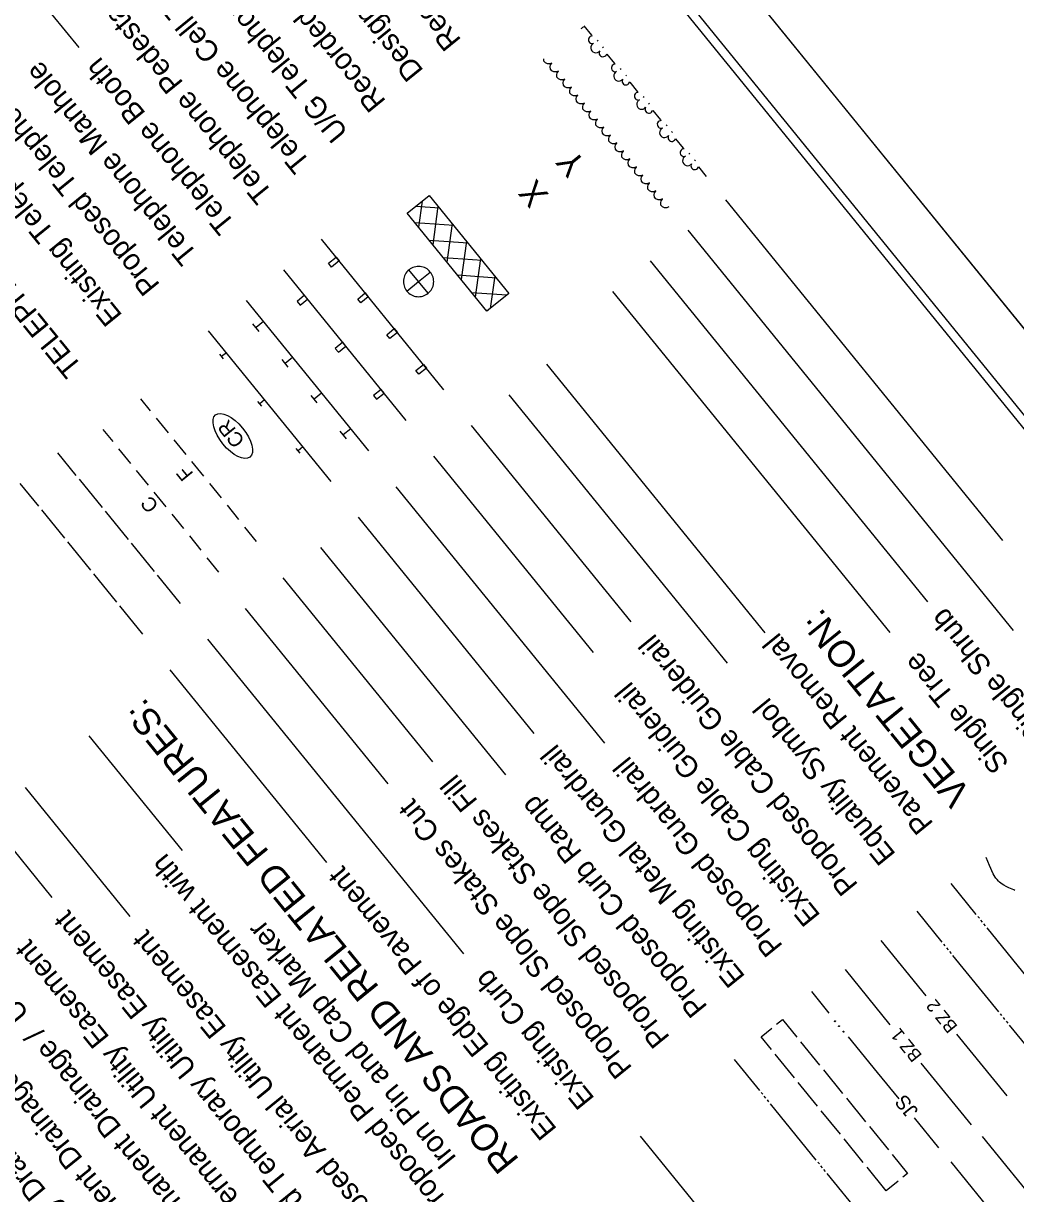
# Model space of a CAD drawing. Extents: x 2596486 to 2602076, y 851390 to 856110.
# Drawn here: x 2599844.2 to 2600253.1, y 854986.6 to 855469.1 of the extents above; entities that cross this region are included whole.
import ezdxf

# ---------------------------------------------------------------- set-up
doc = ezdxf.new("R2010")
doc.units = 0
for name, color, linetype in [('Prop WCC CELL', 7, 'Continuous'), ('Sheet Cutting Line CELL', 7, 'Continuous'), ('Sheet Plot Border Inside CELL', 7, 'Continuous'), ('Sheet Plot Border Outside CELL', 7, 'Continuous'), ('Sheet Symbology CELL', 7, 'Continuous')]:
    doc.layers.add(name, color=color, linetype=linetype)

msp = doc.modelspace()

# ---------------------------------------------------------------- linework, layer by layer
at = {"layer": 'Prop WCC CELL'}
msp.add_ellipse((2599930.44, 855298.98), major_axis=(-7.07, 8.7), ratio=0.462467, dxfattribs=at)
at = {"layer": 'Sheet Cutting Line CELL'}
msp.add_line((2600696, 854802.71), (2599633.88, 856109.52), dxfattribs=at)
at = {"layer": 'Sheet Plot Border Inside CELL'}
msp.add_lwpolyline([(2600670.38, 854798.64), (2599619.29, 856091.87), (2598800.52, 855426.4), (2599851.6, 854133.17)], close=True, dxfattribs=at)
at = {"layer": 'Sheet Plot Border Outside CELL'}
msp.add_lwpolyline([(2600696, 854802.71), (2599633.88, 856109.52), (2598780.26, 855415.74), (2599842.38, 854108.93)], close=True, dxfattribs=at)
at = {"layer": 'Sheet Symbology CELL'}
for p, q in [((2599772.04, 855575.95), (2599866.96, 855459.16)), ((2600078.45, 855464.23), (2600075.3, 855468.11)), ((2600081.08, 855461.79), (2600080.77, 855462.18)), ((2600083.29, 855459.07), (2600082.97, 855459.46)), ((2600058.61, 855454.48), (2600058.62, 855454.55)), ((2600087.91, 855452.59), (2600084.76, 855456.47)), ((2600058.73, 855453.54), (2600058.61, 855454.48)), ((2600059.32, 855452.8), (2600058.73, 855453.54)), ((2600060.18, 855452.47), (2600059.32, 855452.8)), ((2600061.06, 855452.41), (2600060.18, 855452.47)), ((2600061.99, 855452.78), (2600061.06, 855452.41)), ((2600061.29, 855451.18), (2600061.45, 855452.02)), ((2600061.41, 855450.24), (2600061.29, 855451.18)), ((2600062, 855449.51), (2600061.41, 855450.24)), ((2600061.45, 855452.02), (2600061.98, 855452.71)), ((2600090.54, 855450.15), (2600090.23, 855450.54)), ((2600062.86, 855449.17), (2600062, 855449.51)), ((2600063.74, 855449.11), (2600062.86, 855449.17)), ((2600064.67, 855449.48), (2600063.74, 855449.11)), ((2600063.97, 855447.88), (2600064.13, 855448.72)), ((2600064.09, 855446.94), (2600063.97, 855447.88)), ((2600064.69, 855446.21), (2600064.09, 855446.94)), ((2600064.13, 855448.72), (2600064.66, 855449.41)), ((2600065.54, 855445.87), (2600064.69, 855446.21)), ((2600066.42, 855445.81), (2600065.54, 855445.87)), ((2600067.35, 855446.18), (2600066.42, 855445.81)), ((2600066.65, 855444.58), (2600066.81, 855445.42)), ((2600066.81, 855445.42), (2600067.34, 855446.11)), ((2600092.75, 855447.43), (2600092.43, 855447.82)), ((2600066.77, 855443.65), (2600066.65, 855444.58)), ((2600067.37, 855442.91), (2600066.77, 855443.65)), ((2600068.22, 855442.57), (2600067.37, 855442.91)), ((2600069.1, 855442.52), (2600068.22, 855442.57)), ((2600070.03, 855442.88), (2600069.1, 855442.52)), ((2600069.33, 855441.28), (2600069.49, 855442.12)), ((2600069.45, 855440.35), (2600069.33, 855441.28)), ((2600070.05, 855439.61), (2600069.45, 855440.35)), ((2600069.49, 855442.12), (2600070.02, 855442.81)), ((2600097.38, 855440.95), (2600094.22, 855444.83)), ((2600070.9, 855439.27), (2600070.05, 855439.61)), ((2600071.78, 855439.22), (2600070.9, 855439.27)), ((2600072.71, 855439.58), (2600071.78, 855439.22)), ((2600072.01, 855437.99), (2600072.17, 855438.82)), ((2600072.13, 855437.05), (2600072.01, 855437.99)), ((2600072.73, 855436.31), (2600072.13, 855437.05)), ((2600072.17, 855438.82), (2600072.7, 855439.51)), ((2600073.58, 855435.98), (2600072.73, 855436.31)), ((2600074.46, 855435.92), (2600073.58, 855435.98)), ((2600075.39, 855436.29), (2600074.46, 855435.92)), ((2600074.69, 855434.69), (2600074.85, 855435.52)), ((2600074.85, 855435.52), (2600075.38, 855436.22)), ((2600100, 855438.51), (2600099.69, 855438.9)), ((2600102.21, 855435.79), (2600101.89, 855436.18)), ((2600074.81, 855433.75), (2600074.69, 855434.69)), ((2600075.41, 855433.01), (2600074.81, 855433.75)), ((2600076.26, 855432.68), (2600075.41, 855433.01)), ((2600077.14, 855432.62), (2600076.26, 855432.68)), ((2600078.07, 855432.99), (2600077.14, 855432.62)), ((2600077.37, 855431.39), (2600077.53, 855432.23)), ((2600077.49, 855430.45), (2600077.37, 855431.39)), ((2600078.09, 855429.72), (2600077.49, 855430.45)), ((2600077.53, 855432.23), (2600078.06, 855432.92)), ((2600106.84, 855429.31), (2600103.68, 855433.19)), ((2600078.94, 855429.38), (2600078.09, 855429.72)), ((2600079.82, 855429.32), (2600078.94, 855429.38)), ((2600080.75, 855429.69), (2600079.82, 855429.32)), ((2600080.05, 855428.09), (2600080.21, 855428.93)), ((2600080.17, 855427.16), (2600080.05, 855428.09)), ((2600080.77, 855426.42), (2600080.17, 855427.16)), ((2600080.21, 855428.93), (2600080.74, 855429.62)), ((2600081.62, 855426.08), (2600080.77, 855426.42)), ((2600082.51, 855426.03), (2600081.62, 855426.08)), ((2600083.43, 855426.39), (2600082.51, 855426.03)), ((2600082.73, 855424.79), (2600082.89, 855425.63)), ((2600082.89, 855425.63), (2600083.42, 855426.32)), ((2600109.46, 855426.87), (2600109.15, 855427.25)), ((2600082.85, 855423.86), (2600082.73, 855424.79)), ((2600083.45, 855423.12), (2600082.85, 855423.86)), ((2600084.3, 855422.78), (2600083.45, 855423.12)), ((2600085.19, 855422.73), (2600084.3, 855422.78)), ((2600086.11, 855423.09), (2600085.19, 855422.73)), ((2600085.41, 855421.5), (2600085.57, 855422.33)), ((2600085.53, 855420.56), (2600085.41, 855421.5)), ((2600085.57, 855422.33), (2600086.1, 855423.02)), ((2600111.67, 855424.15), (2600111.36, 855424.54)), ((2600116.3, 855417.67), (2600113.14, 855421.55)), ((2600086.13, 855419.82), (2600085.53, 855420.56)), ((2600086.98, 855419.49), (2600086.13, 855419.82)), ((2600087.87, 855419.43), (2600086.98, 855419.49)), ((2600088.79, 855419.8), (2600087.87, 855419.43)), ((2600088.09, 855418.2), (2600088.25, 855419.03)), ((2600088.21, 855417.26), (2600088.09, 855418.2)), ((2600088.81, 855416.52), (2600088.21, 855417.26)), ((2600088.25, 855419.03), (2600088.79, 855419.73)), ((2600089.66, 855416.19), (2600088.81, 855416.52)), ((2600090.55, 855416.13), (2600089.66, 855416.19)), ((2600091.47, 855416.5), (2600090.55, 855416.13)), ((2600090.93, 855415.74), (2600091.47, 855416.43)), ((2600090.78, 855414.9), (2600090.93, 855415.74)), ((2600090.89, 855413.96), (2600090.78, 855414.9)), ((2600091.49, 855413.23), (2600090.89, 855413.96)), ((2600092.34, 855412.89), (2600091.49, 855413.23)), ((2600093.23, 855412.83), (2600092.34, 855412.89)), ((2600094.15, 855413.2), (2600093.23, 855412.83)), ((2600093.46, 855411.6), (2600093.61, 855412.44)), ((2600093.57, 855410.67), (2600093.46, 855411.6)), ((2600093.61, 855412.44), (2600094.15, 855413.13)), ((2600118.92, 855415.23), (2600118.61, 855415.61)), ((2600121.13, 855412.51), (2600120.82, 855412.9)), ((2600094.17, 855409.93), (2600093.57, 855410.67)), ((2600095.03, 855409.59), (2600094.17, 855409.93)), ((2600095.91, 855409.54), (2600095.03, 855409.59)), ((2600096.83, 855409.9), (2600095.91, 855409.54)), ((2600096.14, 855408.3), (2600096.29, 855409.14)), ((2600096.25, 855407.37), (2600096.14, 855408.3)), ((2600096.85, 855406.63), (2600096.25, 855407.37)), ((2600096.29, 855409.14), (2600096.83, 855409.83)), ((2600097.71, 855406.29), (2600096.85, 855406.63)), ((2600098.59, 855406.24), (2600097.71, 855406.29)), ((2600099.51, 855406.6), (2600098.59, 855406.24)), ((2600098.97, 855405.84), (2600099.51, 855406.53)), ((2600125.76, 855406.03), (2600122.6, 855409.91)), ((2600098.82, 855405.01), (2600098.97, 855405.84)), ((2600098.93, 855404.07), (2600098.82, 855405.01)), ((2600099.53, 855403.33), (2600098.93, 855404.07)), ((2600100.39, 855403), (2600099.53, 855403.33)), ((2600101.27, 855402.94), (2600100.39, 855403)), ((2600102.2, 855403.31), (2600101.27, 855402.94)), ((2600101.5, 855401.71), (2600101.65, 855402.54)), ((2600101.61, 855400.77), (2600101.5, 855401.71)), ((2600101.65, 855402.54), (2600102.19, 855403.24)), ((2600002.34, 855390.83), (2600011.42, 855398.21)), ((2600011.42, 855398.21), (2600044.28, 855357.78)), ((2600102.21, 855400.03), (2600101.61, 855400.77)), ((2600103.07, 855399.7), (2600102.21, 855400.03)), ((2600103.95, 855399.64), (2600103.07, 855399.7)), ((2600104.88, 855400.01), (2600103.95, 855399.64)), ((2600104.18, 855398.41), (2600104.34, 855399.25)), ((2600104.29, 855397.47), (2600104.18, 855398.41)), ((2600104.89, 855396.74), (2600104.29, 855397.47)), ((2600104.34, 855399.25), (2600104.87, 855399.94)), ((2600105.75, 855396.4), (2600104.89, 855396.74)), ((2600107.56, 855396.71), (2600106.63, 855396.34)), ((2600107.02, 855395.95), (2600107.55, 855396.64)), ((2600015.74, 855392.9), (2600005.75, 855393.61)), ((2600008.51, 855395.85), (2600007.04, 855385.05)), ((2600015.01, 855393.79), (2600012.9, 855377.83)), ((2600106.63, 855396.34), (2600105.75, 855396.4)), ((2600106.86, 855395.11), (2600107.02, 855395.95)), ((2600106.97, 855394.18), (2600106.86, 855395.11)), ((2600107.57, 855393.44), (2600106.97, 855394.18)), ((2600108.43, 855393.1), (2600107.57, 855393.44)), ((2600109.31, 855393.05), (2600108.43, 855393.1)), ((2600110.24, 855393.41), (2600109.31, 855393.05)), ((2600133.57, 855396.41), (2600247.81, 855255.85)), ((2600035.2, 855350.4), (2600002.34, 855390.83)), ((2600021.57, 855385.72), (2600005.59, 855386.84)), ((2600020.88, 855386.57), (2600018.74, 855370.66)), ((2600118.05, 855383.79), (2600252.2, 855218.75)), ((2600017.51, 855318.04), (2599967.05, 855380.13)), ((2600027.44, 855378.5), (2600011.42, 855379.66)), ((2600026.75, 855379.35), (2600024.57, 855363.48)), ((2600033.31, 855371.28), (2600017.26, 855372.48)), ((2600032.58, 855372.18), (2600030.44, 855356.26)), ((2600102.53, 855371.18), (2600216.77, 855230.62)), ((2600001.99, 855305.43), (2599951.53, 855367.51)), ((2600007.04, 855362.66), (2600003.09, 855367.51)), ((2600007.04, 855362.66), (2600011.89, 855366.6)), ((2600039.14, 855364.11), (2600023.12, 855365.26)), ((2600038.45, 855364.96), (2600036.6, 855351.54)), ((2600002.19, 855358.72), (2600007.04, 855362.66)), ((2600010.98, 855357.81), (2600007.04, 855362.66)), ((2600043.39, 855357.06), (2600028.99, 855358.05)), ((2600087.01, 855358.57), (2600201.25, 855218.01)), ((2599936.01, 855354.9), (2599986.47, 855292.82)), ((2600044.28, 855357.78), (2600035.2, 855350.4)), ((2600035.67, 855350.78), (2600034.85, 855350.83)), ((2599941.32, 855342.1), (2599938.79, 855345.21)), ((2599943.12, 855346.15), (2599940.06, 855343.66)), ((2599970.95, 855280.2), (2599920.49, 855342.28)), ((2599926.66, 855330.73), (2599925.09, 855332.67)), ((2599927.81, 855333.27), (2599925.87, 855331.7)), ((2599953.3, 855327.36), (2599950.78, 855330.46)), ((2599955.1, 855331.4), (2599952.04, 855328.91)), ((2600059.79, 855328.53), (2600149.74, 855217.85)), ((2599965.28, 855312.62), (2599962.76, 855315.72)), ((2599967.09, 855316.66), (2599964.02, 855314.17)), ((2600044.27, 855315.92), (2600134.22, 855205.24)), ((2599892.43, 855314.33), (2599896.47, 855309.36)), ((2599942.43, 855311.32), (2599940.85, 855313.26)), ((2599943.58, 855313.87), (2599941.64, 855312.29)), ((2599898.93, 855306.34), (2599903.88, 855300.25)), ((2599876.91, 855301.72), (2599880.95, 855296.75)), ((2599977.27, 855297.87), (2599974.75, 855300.98)), ((2599979.07, 855301.92), (2599976.01, 855299.42)), ((2600028.75, 855303.3), (2600094.53, 855222.36)), ((2599906.21, 855297.38), (2599911.1, 855291.36)), ((2599865.97, 855282.71), (2599858.4, 855292.02)), ((2599883.41, 855293.72), (2599888.36, 855287.63)), ((2599958.2, 855291.92), (2599956.62, 855293.86)), ((2599959.35, 855294.47), (2599957.41, 855292.89)), ((2600013.23, 855290.69), (2600079.01, 855209.75)), ((2599913.43, 855288.49), (2599918.35, 855282.44)), ((2599876.69, 855269.52), (2599867.23, 855281.16)), ((2599890.69, 855284.76), (2599895.58, 855278.75)), ((2599850.45, 855270.1), (2599842.88, 855279.41)), ((2599920.84, 855279.37), (2599925.64, 855273.47)), ((2599997.71, 855278.07), (2600083.63, 855172.35)), ((2599897.91, 855275.88), (2599902.83, 855269.82)), ((2599861.17, 855256.9), (2599851.71, 855268.54)), ((2599887.42, 855256.33), (2599877.95, 855267.97)), ((2599905.32, 855266.76), (2599910.12, 855260.86)), ((2599928.1, 855270.45), (2599932.86, 855264.59)), ((2599982.19, 855265.46), (2600054.62, 855176.34)), ((2599912.58, 855257.83), (2599917.34, 855251.97)), ((2599940.27, 855255.47), (2599935.48, 855261.37)), ((2599871.9, 855243.71), (2599862.43, 855255.35)), ((2599898.14, 855243.13), (2599888.68, 855254.77)), ((2599966.66, 855253.04), (2600042.93, 855159.2)), ((2599924.75, 855242.86), (2599919.96, 855248.75)), ((2599882.62, 855230.52), (2599873.16, 855242.16)), ((2599908.86, 855229.94), (2599899.4, 855241.58)), ((2599951.14, 855240.43), (2600012.79, 855164.58)), ((2599893.34, 855217.33), (2599883.88, 855228.97)), ((2599935.62, 855227.81), (2599994.4, 855155.5)), ((2599920.1, 855215.2), (2600025.52, 855085.49)), ((2599904.58, 855202.59), (2599969.13, 855123.16)), ((2599871.09, 855175.37), (2599909.57, 855128.02)), ((2599844.84, 855154.03), (2599888.02, 855100.91)), ((2599829.32, 855141.42), (2599855.9, 855108.72)), ((2600236.95, 855101.66), (2600226.56, 855114.44)), ((2600222.89, 855090.23), (2600212.5, 855103.01)), ((2600238.22, 855100.1), (2600237.58, 855100.88)), ((2600239.48, 855098.55), (2600238.85, 855099.33)), ((2600240.74, 855097), (2600240.11, 855097.78)), ((2600260.29, 855072.94), (2600241.37, 855096.22)), ((2600197.61, 855090.91), (2600216.09, 855068.16)), ((2600224.16, 855088.68), (2600223.53, 855089.45)), ((2600225.42, 855087.12), (2600224.79, 855087.9)), ((2600226.68, 855085.57), (2600226.05, 855086.35)), ((2600246.23, 855061.52), (2600227.31, 855084.8)), ((2600182.88, 855078.94), (2600201.36, 855056.2)), ((2600247.49, 855059.96), (2600246.86, 855060.74)), ((2600248.75, 855058.41), (2600248.12, 855059.19)), ((2600250.02, 855056.86), (2600249.38, 855057.64)), ((2600264.54, 855038.99), (2600250.65, 855056.08)), ((2600164.48, 855049.21), (2600172.36, 855039.51)), ((2600249.64, 855026.89), (2600228.96, 855052.33)), ((2600147.66, 855029.08), (2600137.27, 855041.86)), ((2600161.98, 855034.33), (2600154.1, 855044.03)), ((2600234.91, 855014.92), (2600214.23, 855040.36)), ((2600173.94, 855037.57), (2600181.82, 855027.87)), ((2600171.44, 855022.69), (2600163.56, 855032.39)), ((2600148.92, 855027.53), (2600148.29, 855028.3)), ((2600150.18, 855025.97), (2600149.55, 855026.75)), ((2600151.44, 855024.42), (2600150.81, 855025.2)), ((2600183.4, 855025.93), (2600191.28, 855016.23)), ((2600170.99, 855000.37), (2600152.07, 855023.65)), ((2600180.9, 855011.05), (2600173.02, 855020.75)), ((2600192.86, 855014.29), (2600200.74, 855004.59)), ((2600148.92, 854948.25), (2600098.47, 855010.33)), ((2600190.36, 854999.41), (2600182.48, 855009.11)), ((2600239.36, 855010.13), (2600342.64, 854883.06)), ((2600172.25, 854998.81), (2600171.62, 854999.59)), ((2600173.52, 854997.26), (2600172.89, 854998.04)), ((2600174.78, 854995.71), (2600174.15, 854996.49)), ((2600199.82, 854987.76), (2600191.94, 854997.47)), ((2600226.46, 854999.65), (2600309.47, 854897.53)), ((2600189.3, 854977.84), (2600175.41, 854994.93)), ((2600204.71, 854991.74), (2600199.82, 854987.76))]:
    msp.add_line(p, q, dxfattribs=at)
for points in [[(2598810.38, 855418.31), (2599756.45, 854254.29), (2600570.48, 854915.9), (2599624.41, 856079.92)], [(2599971.22, 855368.65), (2599969.96, 855370.2), (2599973.07, 855372.72), (2599974.33, 855371.17)], [(2599961.32, 855355.46), (2599960.06, 855357.02), (2599956.96, 855354.49), (2599958.22, 855352.94)], [(2599983.21, 855353.91), (2599981.95, 855355.46), (2599985.05, 855357.98), (2599986.31, 855356.43)], [(2599995.19, 855339.16), (2599993.93, 855340.71), (2599997.03, 855343.24), (2599998.29, 855341.68)], [(2599977.09, 855336.06), (2599975.83, 855337.62), (2599972.72, 855335.09), (2599973.99, 855333.54)], [(2600007.17, 855324.42), (2600005.91, 855325.97), (2600009.02, 855328.49), (2600010.28, 855326.94)], [(2599992.86, 855316.66), (2599991.6, 855318.22), (2599988.49, 855315.69), (2599989.75, 855314.14)]]:
    msp.add_lwpolyline(points, close=True, dxfattribs=at)
for points in [[(2600252.84, 855111.6), (2600252.35, 855111.82), (2600250.32, 855112.7), (2600249.31, 855113.17), (2600248.33, 855113.7), (2600247.63, 855114.15), (2600247.05, 855114.58), (2600246.56, 855114.99), (2600246.14, 855115.36), (2600245.48, 855116.08), (2600245.02, 855116.64), (2600244.71, 855117.08), (2600244.3, 855117.77), (2600243.94, 855118.49), (2600242.45, 855121.86), (2600240.99, 855125.23)], [(2600176.33, 855061.02), (2600169.13, 855069.88)], [(2600152.52, 855045.97), (2600148.22, 855051.26), (2600152.62, 855054.84)], [(2600154.56, 855056.42), (2600157, 855058.41), (2600162.9, 855051.15)], [(2600196.26, 855036.5), (2600184.28, 855051.24)], [(2600205.11, 855025.62), (2600196.26, 855036.5)], [(2600221.53, 855005.41), (2600211.44, 855017.83)], [(2600202.32, 855002.65), (2600208.61, 854994.91), (2600206.65, 854993.32)]]:
    msp.add_lwpolyline(points, dxfattribs=at)
for centre, radius, start, end in [((2600073.6, 855468.59), 1.58, 285.3538, 332.8518), ((2600078.65, 855462.38), 1.58, 89.8713, 290.6679), ((2600080.08, 855459.04), 2.06, 115.0666, 323.1391), ((2600083.06, 855456.95), 1.58, 147.5378, 348.3343), ((2600088.11, 855450.74), 1.58, 89.8713, 290.6679), ((2600089.54, 855447.39), 2.06, 115.0666, 323.1391), ((2600092.52, 855445.31), 1.58, 147.5378, 348.3343), ((2600097.57, 855439.1), 1.58, 89.8713, 290.6679), ((2600099, 855435.75), 2.06, 115.0666, 323.1391), ((2600101.98, 855433.67), 1.58, 147.5378, 348.3343), ((2600107.03, 855427.46), 1.58, 89.8713, 290.6679), ((2600108.46, 855424.11), 2.06, 115.0666, 323.1391), ((2600111.44, 855422.03), 1.58, 147.5378, 348.3343), ((2600116.49, 855415.82), 1.58, 89.8713, 290.6679), ((2600117.92, 855412.48), 2.06, 115.0666, 323.1391), ((2600120.9, 855410.39), 1.58, 147.5378, 348.3343), ((2600007.04, 855362.66), 6.25, 39.0972, 129.1017), ((2600007.04, 855362.66), 6.25, 129.0972, 219.1017), ((2600007.04, 855362.66), 6.25, 309.0972, 39.1017), ((2600007.04, 855362.66), 6.25, 219.0972, 309.1017)]:
    msp.add_arc(centre, radius, start, end, dxfattribs=at)
for centre in [(2600178.71, 855057.65), (2600180.34, 855055.64), (2600182.21, 855053.35)]:
    msp.add_ellipse(centre, major_axis=(-0.153, -0.124), ratio=0.938496, dxfattribs=at)

# ---------------------------------------------------------------- texts
at = {"layer": 'Prop WCC CELL'}
msp.add_text('CR', height=6, rotation=129.1028, dxfattribs=at).set_placement((2599935.71, 855297.19))
at = {"layer": 'Sheet Symbology CELL'}
for s, height, p in [('Designated U/G Telephone Cable (S.U.E.*)', 8.75, (2600009.39, 855449.66)), ('Recorded U/G Telephone Conduit', 8.75, (2600024.91, 855462.28)), ('Recorded U/G Telephone Cable', 8.75, (2599993.87, 855437.05)), ('U/G Telephone Cable Hand Hole', 8.75, (2599978.35, 855424.43)), ('Telephone Cell Tower', 8.75, (2599962.83, 855411.82)), ('Telephone Pedestal', 8.75, (2599947.31, 855399.19)), ('Proposed Telephone Pole', 8.75, (2599900.75, 855361.35)), ('Telephone Booth', 8.75, (2599931.79, 855386.58)), ('Telephone Manhole', 8.75, (2599916.27, 855373.97)), ('Existing Telephone Pole', 8.75, (2599885.23, 855348.74)), ('Y', 10, (2600076.52, 855411.11)), ('X', 10, (2600061, 855398.5)), ('TELEPHONE:', 8.75, (2599868.74, 855327.52)), ('F', 5.93, (2599914.47, 855283.47)), ('C', 5.93, (2599900.19, 855270.32)), ('Single Shrub', 8.75, (2600266.35, 855176.8)), ('VEGETATION:', 11, (2600235.15, 855151.8)), ('Proposed Cable Guiderail', 8.75, (2600188.52, 855113.92)), ('Pavement Removal', 8.75, (2600219.56, 855139.14)), ('Single Tree', 8.75, (2600250.83, 855164.19)), ('Existing Cable Guiderail', 8.75, (2600173, 855101.3)), ('ROADS AND RELATED FEATURES:', 11, (2600048.85, 855000.58)), ('Equality Symbol', 8.75, (2600204.04, 855126.53)), ('Existing Metal Guardrail', 8.75, (2600141.98, 855076.07)), ('Proposed Guardrail', 8.75, (2600157.48, 855088.69)), ('Proposed Slope Stakes Fill', 8.75, (2600110.93, 855051.04)), ('Proposed Curb Ramp', 8.75, (2600126.45, 855063.65)), ('Proposed Slope Stakes Cut', 8.75, (2600095.41, 855038.43)), ('Proposed Permanent Drainage /  Utility Easement', 8.75, (2599956.74, 854925.72)), ('Proposed Permanent Easement with', 8.75, (2600022.93, 854979.51)), ('Existing Edge of Pavement', 8.75, (2600064.37, 855013.2)), ('Proposed Temporary Utility Easement', 8.75, (2599987.34, 854950.59)), ('Iron Pin and Cap Marker', 8.75, (2600023.03, 855001.19)), ('Proposed Aerial Utility Easement', 8.75, (2600002.86, 854963.2)), ('Proposed Permanent Utility Easement', 8.75, (2599971.82, 854937.97)), ('Proposed Permanent Drainage Easement', 8.75, (2599940.77, 854912.74)), ('Existing Curb', 8.75, (2600079.89, 855025.81)), ('Proposed Temporary Construction Easement', 8.75, (2599909.73, 854887.51)), ('Proposed Temporary Drainage Easement', 8.75, (2599925.25, 854900.13)), ('BZ 2', 5.315, (2600229.49, 855055.54)), ('BZ 1', 5.315, (2600214.82, 855043.62)), ('JS', 5.905, (2600213.32, 855020.79))]:
    msp.add_text(s, height=height, rotation=129.1028, dxfattribs=at).set_placement(p)

doc.saveas('drawing.dxf')
